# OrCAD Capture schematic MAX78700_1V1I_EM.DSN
size Custom; title: MAX78700: 1V1I Board with Shunt; rev: 1; company: Maxim Integrated - Energy Solutions; note: Board with shunt
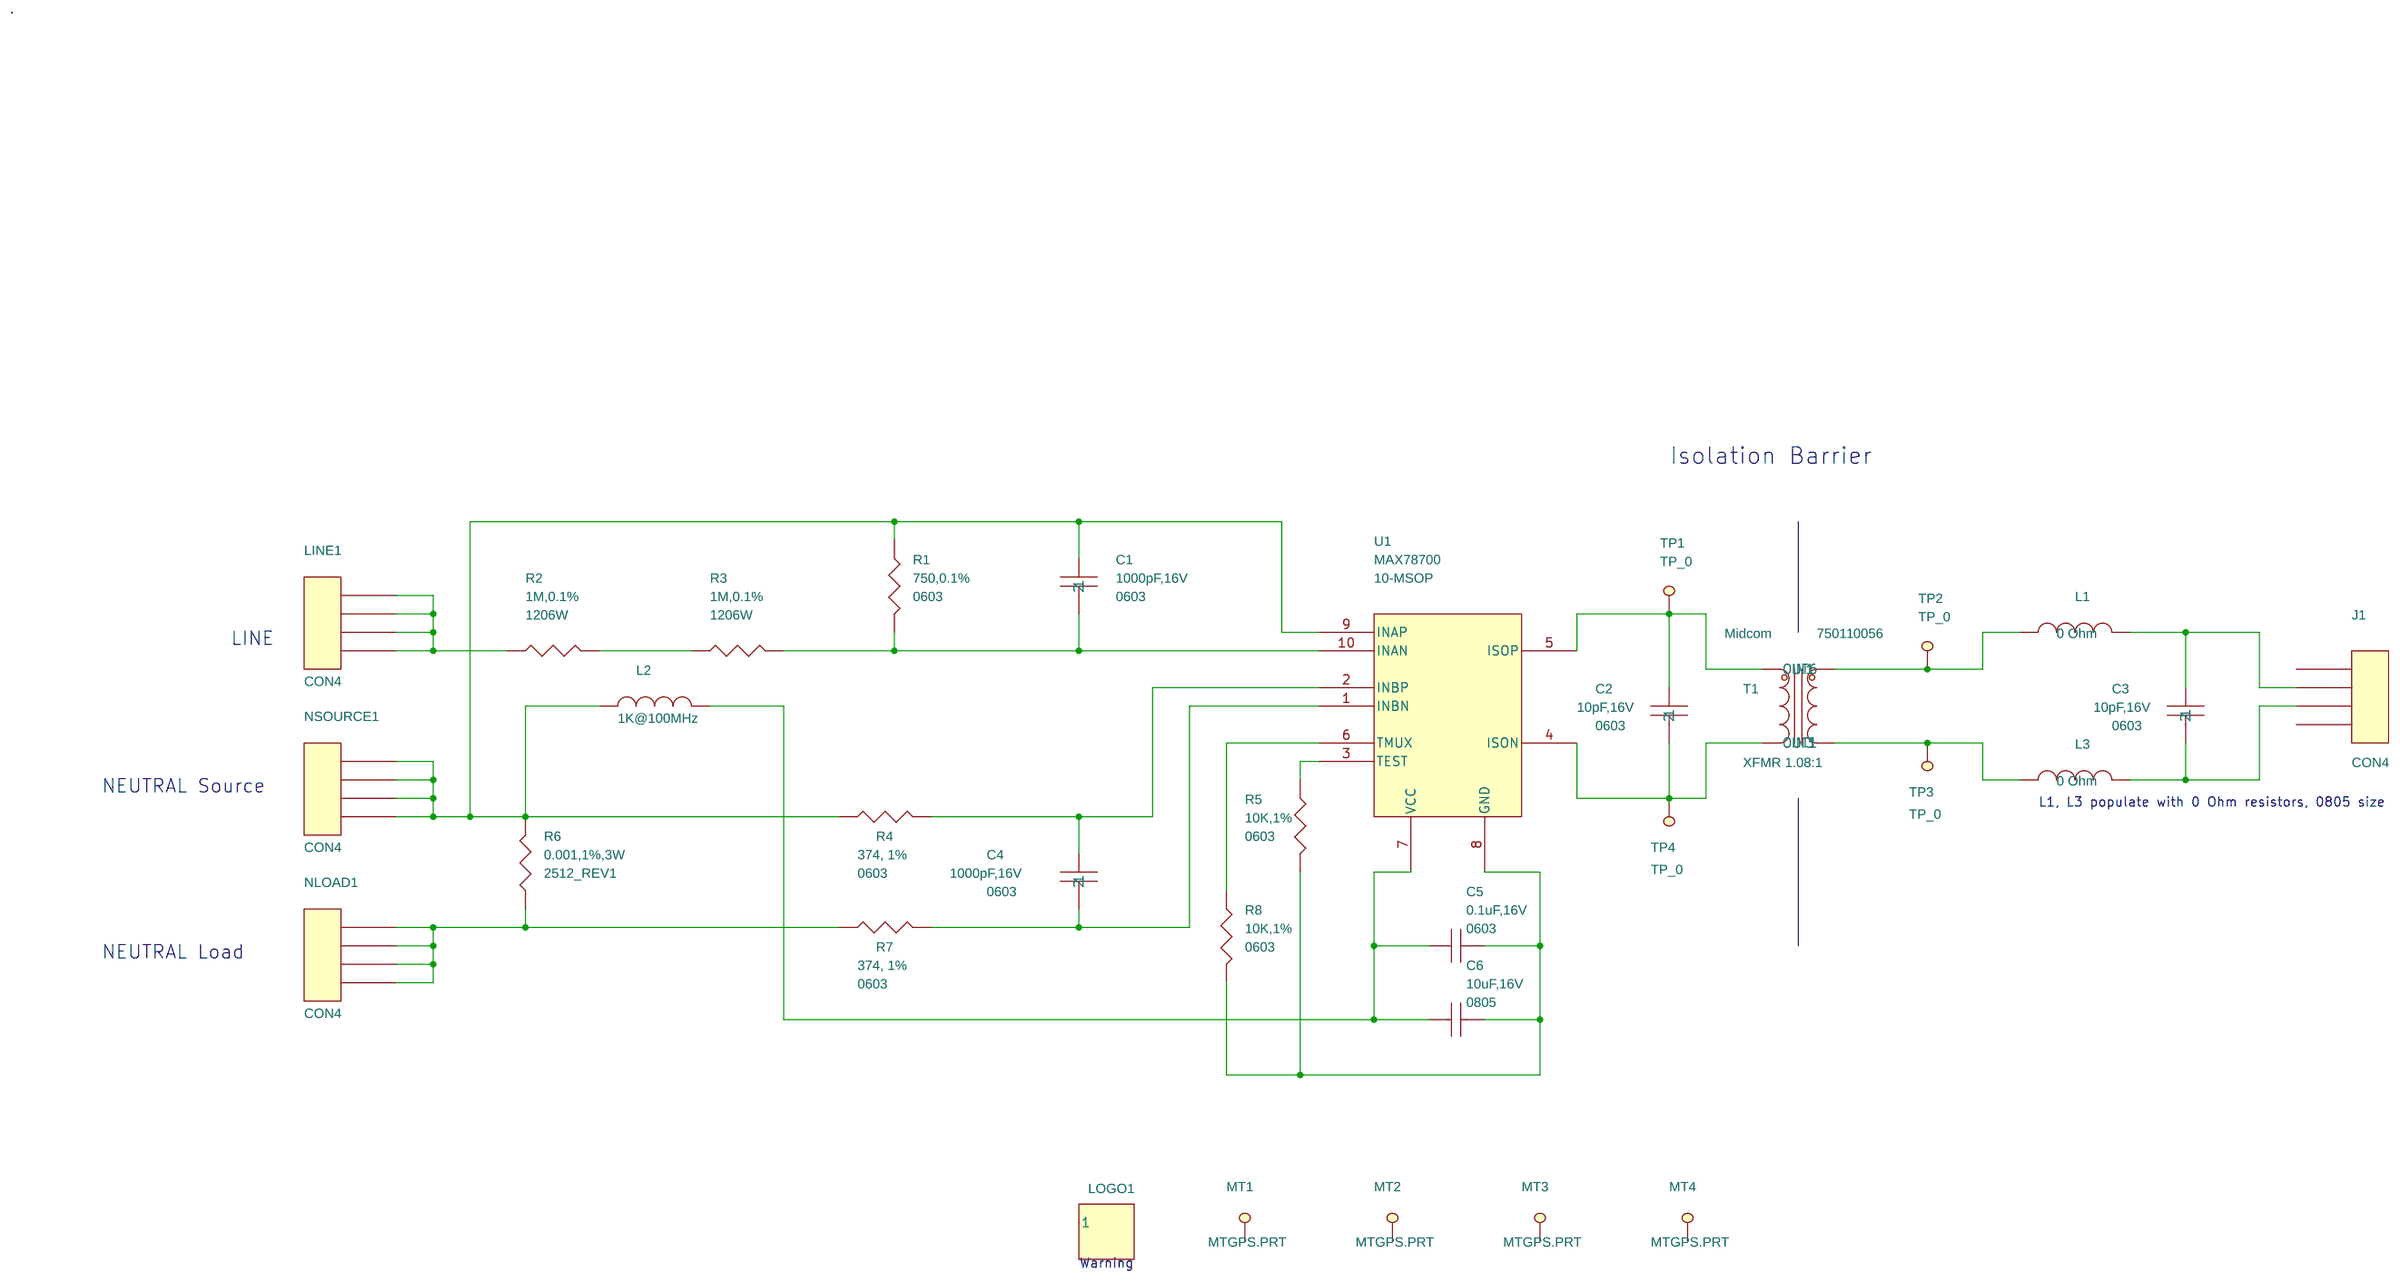
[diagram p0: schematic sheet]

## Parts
C1  1000pF,16V  [0603]
C2  10pF,16V  [0603]
C3  10pF,16V  [0603]
C4  1000pF,16V  [0603]
C5  0.1uF,16V  [0603]
C6  10uF,16V  [0805]
J1  CON4
L1  0 Ohm  [0805]
L2  1K@100MHz  [0805]
L3  0 Ohm  [0805]
LINE1  CON4  [STERM]
LOGO1  HEADER 2  [WARNING]
MT1  TP  [MTGPS.PRT]
MT2  TP  [MTGPS.PRT]
MT3  TP  [MTGPS.PRT]
MT4  TP  [MTGPS.PRT]
NLOAD1  CON4  [STERM]
NSOURCE1  CON4  [STERM]
R1  750,0.1%  [0603]
R2  1M,0.1%  [1206W]
R3  1M,0.1%  [1206W]
R4  374, 1%  [0603]
R5  10K,1%  [0603]
R6  0.001,1%,3W  [2512_REV1]
R7  374, 1%  [0603]
R8  10K,1%  [0603]
T1  XFMR 1.08:1  [2253-XFMRB]
TP1  TP_0  [SIP\1P]
TP2  TP_0  [SIP\1P]
TP3  TP_0  [SIP\1P]
TP4  TP_0  [SIP\1P]
U1  MAX78700  [10-MSOP]

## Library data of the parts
C1 = C: COMPFIXED: NO; COMPGROUP: 0; COMPHEIGHT: 0.000; COMPKEY: NO; COMPLOC: [-1475.000,19750.000]; COMPLOCKED: NO; COMPROT: 180; COMPSIDE: BOT; DECOUPLER: NO; Digi-Key PN: 399-7933-1-ND; FPLIST: 0805; MEMORY: NO; Manufacturer: Kemet; Manufacturer PN: C0603C473K5RACTU; Rating: 50V; Tolerance: 10%
C2 = C_3: COMPFIXED: NO; COMPGROUP: 0; COMPHEIGHT: 0.000; COMPKEY: NO; COMPLOC: [-1475.000,19750.000]; COMPLOCKED: NO; COMPROT: 180; COMPSIDE: BOT; DECOUPLER: NO; Digi-Key PN: 445-1269-1-ND; FPLIST: 0805; MEMORY: NO; Manufacturer: TDK Corporation; Manufacturer PN: C1608C0G1H100D080AA; Rating: 50V
C3 = C_2: COMPFIXED: NO; COMPGROUP: 0; COMPHEIGHT: 0.000; COMPKEY: NO; COMPLOC: [-1475.000,19750.000]; COMPLOCKED: NO; COMPROT: 180; COMPSIDE: BOT; DECOUPLER: NO; Digi-Key PN: 445-1269-1-ND; FPLIST: 0805; MEMORY: NO; Manufacturer: TDK Corporation; Manufacturer PN: C1608C0G1H100D080AA; Rating: 50V
C4 = C_1: COMPFIXED: NO; COMPGROUP: 0; COMPHEIGHT: 0.000; COMPKEY: NO; COMPLOC: [-1475.000,19750.000]; COMPLOCKED: NO; COMPROT: 180; COMPSIDE: BOT; DECOUPLER: NO; Digi-Key PN: 399-7933-1-ND; FPLIST: 0805; MEMORY: NO; Manufacturer: Kemet; Manufacturer PN: C0603C473K5RACTU; Rating: 50V; Tolerance: 10%
C5 = CAP_NP: COMPFIXED: NO; COMPGROUP: 0; COMPHEIGHT: 0.000; COMPKEY: NO; COMPLOC: [-1552.000,1919.000]; COMPLOCKED: NO; COMPROT: 0; COMPSIDE: TOP; DECOUPLER: NO; Digi-Key PN: 445-1314-1-ND; MEMORY: NO; Manufacturer: TDK Corporation; Manufacturer PN: C1608X7R1H104K080AA; Rating: 50V; Tolerance: 10%
C6 = CAP_NP: COMPFIXED: NO; COMPGROUP: 0; COMPHEIGHT: 0.000; COMPKEY: NO; COMPLOC: [-1552.000,1919.000]; COMPLOCKED: NO; COMPROT: 0; COMPSIDE: TOP; DECOUPLER: NO; Digi-Key PN: 399-1170-1-ND; MEMORY: NO; Manufacturer: Kemet; Manufacturer PN: C0805C104K5RACTU; Rating: 50V; Tolerance: 10%
J1 = CON4: Digi-Key PN: S1011E-36-ND; HDR: 0.11; Manufacturer: Sullins Connector Solutions; Manufacturer PN: PBC36SAAN
L1-L3 = INDUCTOR: Digi-Key PN: A102197CT-ND; Manufacturer: TE Connectivity; Manufacturer PN: 2-1624117-0; Rating: 350mA
LINE1 NLOAD1 NSOURCE1 = CON4: Digi-Key PN: 8191K-ND; Manufacturer: Keystone Electronics; Manufacturer PN: 8191
LOGO1 = HEADER_2_3: COMPFIXED: NO; COMPGROUP: 0; COMPHEIGHT: 0.000; COMPKEY: NO; COMPLOC: [350.000,-650.000]; COMPLOCKED: NO; COMPROT: 0; COMPSIDE: TOP; DECOUPLER: NO; DNP: DNP; MEMORY: NO
MT1-MT4 = TP_0: COMPFIXED: NO; COMPGROUP: 0; COMPHEIGHT: 0.000; COMPKEY: NO; COMPLOC: [2200.000,175.000]; COMPLOCKED: NO; COMPROT: 0; COMPSIDE: TOP; DECOUPLER: NO; DNP: DNP; FPLIST: MTG.PRT,TESTPOINT,SIP\1P; MEMORY: NO
R1 = RESISTOR: COMPFIXED: NO; COMPGROUP: 0; COMPHEIGHT: 0.000; COMPKEY: NO; COMPLOC: [4450.000,1610.000]; COMPLOCKED: NO; COMPROT: 90; COMPSIDE: TOP; DECOUPLER: NO; Digi-Key PN: RG16P750BCT-ND; FPLIST: 0805; MEMORY: NO; Manufacturer: Susumu; Manufacturer PN: RG1608P-751-B-T5; Rating: 1/10W; Tolerance: 0.1%
R2 = RESISTOR: COMPFIXED: NO; COMPGROUP: 0; COMPHEIGHT: 0.000; COMPKEY: NO; COMPLOC: [193.500,325.000]; COMPLOCKED: NO; COMPROT: 180; COMPSIDE: BOT; DECOUPLER: NO; FPLIST: X273RC,0805; MEMORY: NO; Manufacturer: KOA Speer; Manufacturer PN: RN732BTTD1004B25; Mouser: 660-RN732BTTD1004B25; Rating: 1/4W; Tolerance: 0.1%
R3 = RESISTOR: COMPFIXED: NO; COMPGROUP: 0; COMPHEIGHT: 0.000; COMPKEY: NO; COMPLOC: [425.000,450.000]; COMPLOCKED: NO; COMPROT: 270; COMPSIDE: BOT; DECOUPLER: NO; FPLIST: X273RC,0805; MEMORY: NO; Manufacturer: KOA Speer; Manufacturer PN: RN732BTTD1004B25; Mouser: 660-RN732BTTD1004B25; Rating: 1/4W; Tolerance: 0.1%
R4 R7 = RESISTOR: COMPFIXED: NO; COMPGROUP: 0; COMPHEIGHT: 0.000; COMPKEY: NO; COMPLOC: [6150.000,730.000]; COMPLOCKED: NO; COMPROT: 180; COMPSIDE: TOP; DECOUPLER: NO; Digi-Key PN: 445-1293-6-ND; MEMORY: NO; Manufacturer: TDK Corporation; Manufacturer PN: C1608C0G1H102J080AA; Rating: 1/10W; Tolerance: 0.1%
R5 R8 = RESISTOR: COMPFIXED: NO; COMPGROUP: 0; COMPHEIGHT: 0.000; COMPKEY: NO; COMPLOC: [4450.000,1610.000]; COMPLOCKED: NO; COMPROT: 90; COMPSIDE: TOP; DECOUPLER: NO; Digi-Key PN: P10.0KHCT-ND; FPLIST: 0805; MEMORY: NO; Manufacturer: Panasonic; Manufacturer PN: ERJ-3EKF1002V; Rating: 1/10W; Tolerance: 1%
R6 = RESISTOR: COMPFIXED: NO; COMPGROUP: 0; COMPHEIGHT: 0.000; COMPKEY: NO; COMPLOC: [1100.000,825.000]; COMPLOCKED: NO; COMPROT: 0; COMPSIDE: TOP; DECOUPLER: NO; Digi-Key PN: 696-1185-6-ND; FPLIST: 1206,0805; MEMORY: NO; Manufacturer: Riedon; Manufacturer PN: CSR2512C0R001F; Rating: 3W; Tolerance: 1%
T1 = XFMRCT_0: COMPFIXED: NO; COMPGROUP: 0; COMPHEIGHT: 0.000; COMPKEY: NO; COMPLOC: [6100.000,4200.000]; COMPLOCKED: NO; COMPROT: 180; COMPSIDE: TOP; DECOUPLER: NO; MEMORY: NO; Manufacturer: Midcom; Manufacturer PN: 750110056
TP1-TP4 = TP_0: DNP: DNP
U1 = AM81A: Manufacturer: Maxim Integrated

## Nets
N22634142: C1.2 R1.2 R3.2 U1.10(INAN)
N22642528: C5.1 C6.1 L2.2 U1.7(VCC)
N22651581: R8.1 U1.6(TMUX)
N22660063: C4.2 R7.2 U1.1(INBN)
N22661062: C4.1 R4.2 U1.2(INBP)
N22669136: LINE1.1 LINE1.2 LINE1.3 LINE1.4 R2.1
N22688646: NLOAD1.1 NLOAD1.2 NLOAD1.3 NLOAD1.4 R6.1 R7.1
N22692467: C1.1 L2.1 NSOURCE1.1 NSOURCE1.2 NSOURCE1.3 NSOURCE1.4 R1.1 R4.1 R6.2 U1.9(INAP)
N22731568: C2.2 T1.4(OUT1) TP4.1 U1.4(ISON)
N22732826: C2.1 T1.6(OUT6) TP1.1 U1.5(ISOP)
N22744893: C5.2 C6.2 R5.2 R8.2 U1.8(GND)
N23344720: R2.2 R3.1
N23353708: L1.1 T1.1(IN1) TP2.1
N23353713: L3.1 T1.3(IN3) TP3.1
N23353718: C3.1 J1.2 L1.2
N23353723: C3.2 J1.3 L3.2
N23354890: R5.1 U1.3(TEST)

Not connected (* = marked no-connect by the designer): J1 1 4; LOGO1 1; MT1 1; MT2 1; MT3 1; MT4 1

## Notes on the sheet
- .
- Isolation Barrier
- LINE
- NEUTRAL Source
- L1, L3 populate with 0 Ohm resistors, 0805 size
- NEUTRAL Load
- Warning
